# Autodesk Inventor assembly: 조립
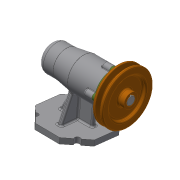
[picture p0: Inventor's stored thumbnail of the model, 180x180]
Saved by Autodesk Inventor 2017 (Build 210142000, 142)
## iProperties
Created: 2019-12
Part Number: 조립
Document SubType Name: Assembly
Designer: 5-02-le
Author: 5-02-le
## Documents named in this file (12)
- C:\Users\5-02-le\Desktop\491204V1003\조립.iam
- C:\Users\5-02-le\Desktop\491204V1003\본체.ipt
- C:\Users\5-02-le\Desktop\491204V1003\오일 실.ipt
- C:\Users\5-02-le\Desktop\491204V1003\축.ipt
- C:\Users\5-02-le\Desktop\491204V1003\커버.ipt
- C:\Users\5-02-le\Desktop\491204V1003\키 5 x 5 x 16.ipt
- C:\Users\5-02-le\Desktop\491204V1003\볼트 M4.ipt
- C:\Users\5-02-le\Desktop\491204V1003\어댑터슬리브.ipt
- C:\Users\5-02-le\Desktop\491204V1003\V벨트풀리.ipt
- C:\Users\5-02-le\Desktop\491204V1003\멈춤나사 M3.ipt
- C:\Users\5-02-le\Desktop\491204V1003\베어링 6004.ipt
- C:\Users\5-02-le\Desktop\491204V1003\베어링 51202.ipt
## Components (1 placed, 1 different names)
1. V벨트풀리:1
